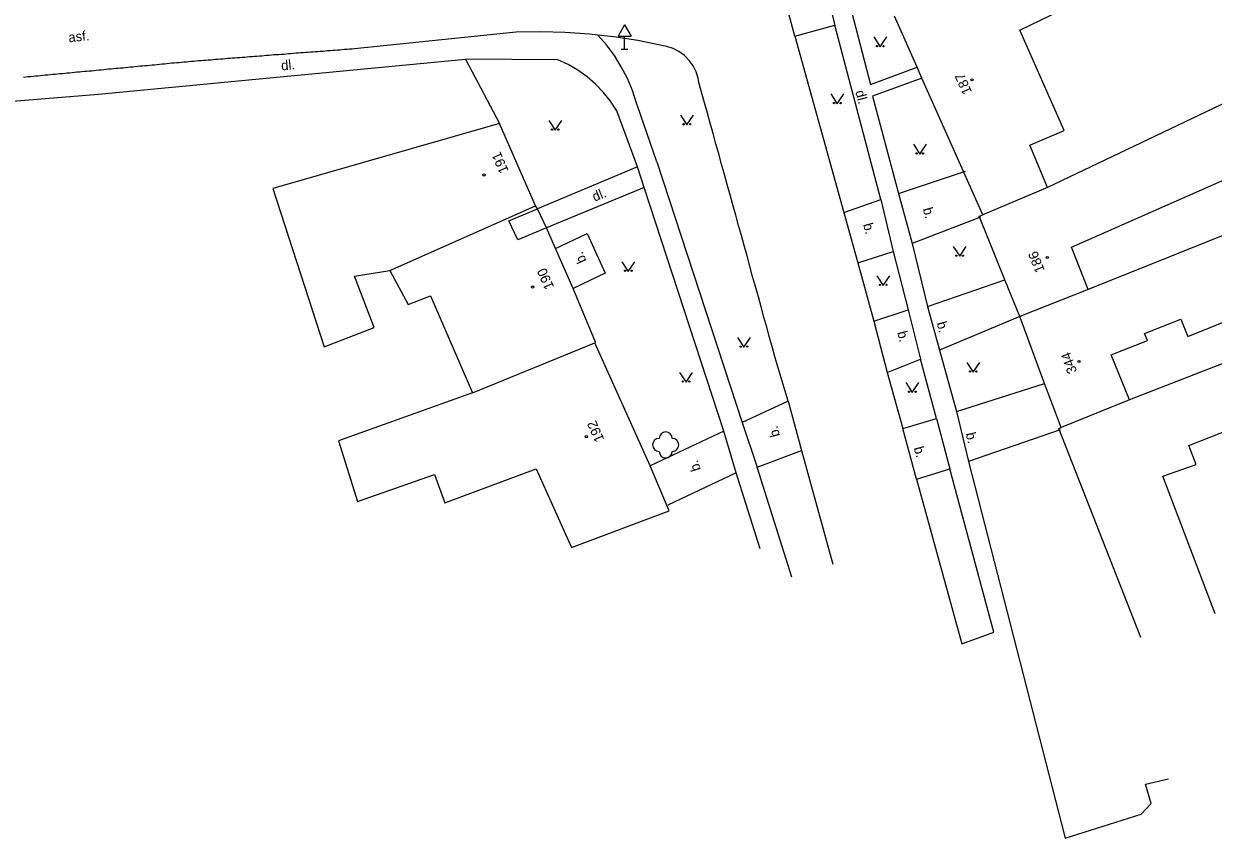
# Model space of a CAD drawing. Extents: x -536391 to -535419, y -1201788 to -1200779.
# Drawn here: x -535590.1 to -535498.7, y -1201665.1 to -1201602.5 of the extents above; entities that cross this region are included whole.
import ezdxf

# ---------------------------------------------------------------- set-up
doc = ezdxf.new("R2010")
doc.units = 0
for name, color, linetype in [('BUDOVY_MĚŘ', 7, 'Continuous'), ('BUDOVY_NEMĚŘ', 7, 'Continuous'), ('POMOC_POPIS', 7, 'Continuous'), ('ROZHRANÍ_PLOCH', 7, 'Continuous'), ('ZELEŇ', 7, 'Continuous'), ('ZN_BUDOV', 7, 'Continuous'), ('ZN_DOPLŇKOVÉ', 7, 'Continuous'), ('ZN_KULTUR', 7, 'Continuous'), ('Č_POPIS_ORIENT', 7, 'Continuous')]:
    doc.layers.add(name, color=color, linetype=linetype)

msp = doc.modelspace()

# ---------------------------------------------------------------- linework, layer by layer
at = {"layer": 'BUDOVY_MĚŘ'}
for points in [[(-535516.38, -1201617.2), (-535521.06, -1201606.7), (-535521.43, -1201605.87), (-535523.18, -1201601.94)], [(-535553.51, -1201610.19), (-535570.93, -1201615.18)], [(-535550.76, -1201616.51), (-535553.51, -1201610.19)], [(-535549.91, -1201618.2), (-535552.12, -1201619.12), (-535552.8, -1201617.68), (-535550.61, -1201616.74)], [(-535550.61, -1201616.74), (-535550.76, -1201616.51)], [(-535549.91, -1201618.2), (-535550.61, -1201616.74)], [(-535513.53, -1201625.03), (-535514.68, -1201622.21), (-535516.66, -1201617.32), (-535516.38, -1201617.2)], [(-535546.2, -1201627.04), (-535546.14, -1201627), (-535547.86, -1201622.88), (-535549.21, -1201619.8), (-535549.91, -1201618.2)], [(-535510.36, -1201633.56), (-535511.63, -1201630.16), (-535513.53, -1201625.03)], [(-535540.48, -1201639.96), (-535541.93, -1201636.51), (-535546.2, -1201627.04)], [(-535504.24, -1201649.68), (-535510.54, -1201633.63), (-535510.36, -1201633.56)]]:
    msp.add_lwpolyline(points, dxfattribs=at)
at = {"layer": 'BUDOVY_NEMĚŘ'}
for points in [[(-535511.42, -1201615.11), (-535512.76, -1201611.86), (-535510.13, -1201610.73), (-535513.53, -1201603.02), (-535501.82, -1201597.33), (-535501.47, -1201598.07), (-535500.97, -1201597.79), (-535502.17, -1201595.2), (-535503.72, -1201591.89), (-535522.9, -1201601.79)], [(-535508.29, -1201622.96), (-535509.57, -1201619.7), (-535497.15, -1201614.22), (-535497.36, -1201613.69), (-535491.66, -1201611.18), (-535493.68, -1201606.66), (-535511.42, -1201615.11), (-535516.38, -1201617.2)], [(-535505.12, -1201631.43), (-535506.53, -1201627.98), (-535503.73, -1201626.88), (-535503.95, -1201626.32), (-535501.16, -1201625.22), (-535500.63, -1201626.56), (-535492.18, -1201623.16), (-535492.7, -1201621.86), (-535491.84, -1201621.47), (-535492.19, -1201620.68), (-535480.05, -1201614.49), (-535476.82, -1201612.92), (-535479.05, -1201608.98), (-535482.17, -1201610.77), (-535494.6, -1201617.48), (-535508.29, -1201622.96), (-535513.53, -1201625.03)], [(-535570.93, -1201615.18), (-535567, -1201627.35), (-535563.15, -1201625.88), (-535564.66, -1201621.92), (-535561.95, -1201621.48), (-535550.76, -1201616.51)], [(-535561.95, -1201621.48), (-535560.53, -1201624.09), (-535558.82, -1201623.43), (-535555.6, -1201630.89), (-535546.2, -1201627.04)], [(-535498.53, -1201647.88), (-535502.55, -1201637.28), (-535499.99, -1201636.39), (-535500.56, -1201634.94), (-535486.94, -1201629.59), (-535488.98, -1201625.15), (-535505.12, -1201631.43), (-535510.36, -1201633.56)], [(-535555.6, -1201630.89), (-535565.88, -1201634.58), (-535564.42, -1201639.23), (-535558.52, -1201637.16), (-535557.71, -1201639.34), (-535550.71, -1201636.72), (-535547.98, -1201642.76), (-535540.48, -1201639.96)]]:
    msp.add_lwpolyline(points, dxfattribs=at)
at = {"layer": 'ROZHRANÍ_PLOCH'}
for points in [[(-535530.74, -1201585.15), (-535525.02, -1201607.19), (-535521.43, -1201605.87)], [(-535528.76, -1201598.67), (-535527.76, -1201602.65)], [(-535530.83, -1201603.48), (-535531.87, -1201599.53)], [(-535530.83, -1201603.48), (-535527.76, -1201602.65)], [(-535524.22, -1201616.04), (-535527.76, -1201602.65)], [(-535545.95, -1201603.4), (-535546.6, -1201603.33), (-535548.48, -1201603.2), (-535550.35, -1201603.15), (-535552.23, -1201603.18), (-535564.67, -1201604.46), (-535564.86, -1201604.48), (-535565.04, -1201604.49), (-535565.23, -1201604.5), (-535565.42, -1201604.52), (-535565.61, -1201604.53), (-535565.79, -1201604.55), (-535565.98, -1201604.56), (-535566.17, -1201604.58), (-535566.36, -1201604.59), (-535566.54, -1201604.6), (-535566.73, -1201604.62), (-535566.92, -1201604.63), (-535567.1, -1201604.65), (-535567.29, -1201604.66), (-535567.48, -1201604.68), (-535567.67, -1201604.69), (-535567.85, -1201604.7), (-535568.04, -1201604.72), (-535568.23, -1201604.73), (-535568.41, -1201604.75), (-535568.6, -1201604.76), (-535568.79, -1201604.77), (-535568.98, -1201604.79), (-535569.16, -1201604.8), (-535569.35, -1201604.82), (-535569.54, -1201604.83), (-535569.72, -1201604.85), (-535569.91, -1201604.86), (-535570.1, -1201604.88), (-535570.29, -1201604.89), (-535570.47, -1201604.91), (-535570.66, -1201604.92), (-535570.85, -1201604.93), (-535571.03, -1201604.95), (-535571.22, -1201604.96), (-535571.41, -1201604.98), (-535571.59, -1201604.99), (-535571.78, -1201605.01), (-535571.97, -1201605.02), (-535572.16, -1201605.04), (-535572.34, -1201605.05), (-535572.53, -1201605.07), (-535572.72, -1201605.08), (-535572.9, -1201605.09), (-535573.09, -1201605.11), (-535573.28, -1201605.12), (-535573.47, -1201605.14), (-535573.65, -1201605.15), (-535573.84, -1201605.17), (-535574.03, -1201605.18), (-535574.21, -1201605.2), (-535574.4, -1201605.21), (-535574.59, -1201605.23), (-535574.78, -1201605.24), (-535574.96, -1201605.25), (-535575.15, -1201605.27), (-535575.34, -1201605.28), (-535575.52, -1201605.3), (-535575.71, -1201605.32), (-535575.9, -1201605.33), (-535576.09, -1201605.34), (-535576.27, -1201605.36), (-535576.46, -1201605.37), (-535576.65, -1201605.39), (-535576.83, -1201605.4), (-535577.02, -1201605.42), (-535577.21, -1201605.43), (-535577.4, -1201605.45), (-535577.58, -1201605.47), (-535577.77, -1201605.49), (-535577.95, -1201605.5), (-535578.14, -1201605.52), (-535578.33, -1201605.54), (-535578.52, -1201605.56), (-535578.7, -1201605.57), (-535578.89, -1201605.59), (-535579.08, -1201605.61), (-535579.26, -1201605.63), (-535579.45, -1201605.64), (-535579.64, -1201605.66), (-535579.82, -1201605.68), (-535580.01, -1201605.7), (-535580.2, -1201605.72), (-535580.38, -1201605.73), (-535580.57, -1201605.75), (-535580.76, -1201605.77), (-535580.94, -1201605.79), (-535581.13, -1201605.8), (-535581.32, -1201605.82), (-535581.51, -1201605.84), (-535581.69, -1201605.86), (-535581.88, -1201605.87), (-535582.07, -1201605.89), (-535582.25, -1201605.91), (-535582.44, -1201605.93)], [(-535533.41, -1201624.29), (-535533.63, -1201623.5), (-535533.85, -1201622.72), (-535534.07, -1201621.94), (-535534.28, -1201621.15), (-535534.5, -1201620.37), (-535534.72, -1201619.58), (-535534.93, -1201618.8), (-535535.15, -1201618.02), (-535535.37, -1201617.23), (-535535.59, -1201616.45), (-535535.8, -1201615.67), (-535536.02, -1201614.88), (-535536.24, -1201614.1), (-535536.45, -1201613.31), (-535536.67, -1201612.53), (-535536.89, -1201611.75), (-535537.11, -1201610.96), (-535537.32, -1201610.18), (-535537.54, -1201609.4), (-535537.76, -1201608.61), (-535538.19, -1201607.04), (-535538.25, -1201606.71), (-535538.41, -1201606.22), (-535538.65, -1201605.76), (-535538.95, -1201605.34), (-535539.31, -1201604.98), (-535539.73, -1201604.67), (-535540.18, -1201604.43), (-535540.67, -1201604.27), (-535541.04, -1201604.19), (-535542.88, -1201603.82), (-535544.74, -1201603.53), (-535545.95, -1201603.4)], [(-535541.42, -1201613.13), (-535542.92, -1201608.83), (-535542.98, -1201608.63), (-535543.3, -1201607.67), (-535543.69, -1201606.73), (-535544.16, -1201605.83), (-535544.69, -1201604.97), (-535545.3, -1201604.16), (-535545.95, -1201603.4)], [(-535530.83, -1201603.48), (-535527.05, -1201617.02)], [(-535542.91, -1201613.52), (-535544.5, -1201609.21), (-535544.98, -1201608.48), (-535545.52, -1201607.8), (-535546.13, -1201607.17), (-535546.79, -1201606.6), (-535547.5, -1201606.1), (-535548.25, -1201605.66), (-535549.04, -1201605.29), (-535556.13, -1201605.24)], [(-535582.44, -1201605.93), (-535582.63, -1201605.95), (-535582.81, -1201605.96), (-535583, -1201605.98), (-535583.19, -1201606), (-535583.37, -1201606.01), (-535583.56, -1201606.03), (-535583.75, -1201606.05), (-535583.93, -1201606.07), (-535584.12, -1201606.09), (-535584.31, -1201606.1), (-535584.5, -1201606.12), (-535584.68, -1201606.14), (-535584.87, -1201606.16), (-535585.06, -1201606.17), (-535585.24, -1201606.19), (-535585.43, -1201606.21), (-535585.62, -1201606.23), (-535585.8, -1201606.25), (-535585.99, -1201606.26), (-535586.18, -1201606.28), (-535586.36, -1201606.3), (-535586.55, -1201606.32), (-535586.74, -1201606.33), (-535586.92, -1201606.35), (-535587.11, -1201606.37), (-535587.3, -1201606.39), (-535587.48, -1201606.4), (-535587.67, -1201606.42), (-535587.86, -1201606.44), (-535588.04, -1201606.46), (-535588.23, -1201606.48), (-535588.42, -1201606.49), (-535588.61, -1201606.51), (-535588.79, -1201606.53), (-535588.98, -1201606.55), (-535589.17, -1201606.56), (-535589.35, -1201606.58), (-535589.54, -1201606.6), (-535589.73, -1201606.62), (-535589.91, -1201606.63), (-535590.1, -1201606.65)], [(-535521.06, -1201606.7), (-535524.87, -1201608.1), (-535522.85, -1201615.58), (-535517.7, -1201613.86)], [(-535542.91, -1201613.52), (-535550.61, -1201616.74)], [(-535542.41, -1201615.11), (-535542.91, -1201613.52)], [(-535541.42, -1201613.13), (-535534.86, -1201633.17)], [(-535542.41, -1201615.11), (-535549.91, -1201618.2)], [(-535536.29, -1201633.84), (-535542.41, -1201615.11)], [(-535522.85, -1201615.58), (-535521.82, -1201619.42)], [(-535527.05, -1201617.02), (-535524.22, -1201616.04)], [(-535524.22, -1201616.04), (-535523.27, -1201620.02)], [(-535527.05, -1201617.02), (-535525.99, -1201620.9)], [(-535516.55, -1201617.4), (-535521.82, -1201619.42)], [(-535549.21, -1201619.8), (-535546.79, -1201618.64), (-535545.39, -1201621.69), (-535547.86, -1201622.88)], [(-535525.99, -1201620.9), (-535523.27, -1201620.02)], [(-535523.27, -1201620.02), (-535522.12, -1201624.5)], [(-535521.82, -1201619.42), (-535520.62, -1201624.25), (-535514.68, -1201622.21)], [(-535525.99, -1201620.9), (-535524.75, -1201625.39)], [(-535531.34, -1201631.54), (-535532.33, -1201628.21), (-535532.55, -1201627.42), (-535532.76, -1201626.64), (-535532.98, -1201625.85), (-535533.2, -1201625.07), (-535533.41, -1201624.29)], [(-535524.75, -1201625.39), (-535522.12, -1201624.5)], [(-535522.12, -1201624.5), (-535521.16, -1201628.3)], [(-535520.62, -1201624.25), (-535519.71, -1201627.6)], [(-535524.75, -1201625.39), (-535523.74, -1201629.32)], [(-535513.53, -1201625.03), (-535519.71, -1201627.6), (-535518.4, -1201632.31), (-535511.63, -1201630.16)], [(-535523.74, -1201629.32), (-535521.16, -1201628.3)], [(-535522.53, -1201633.64), (-535519.95, -1201632.86), (-535521.16, -1201628.3)], [(-535523.74, -1201629.32), (-535522.53, -1201633.64)], [(-535531.34, -1201631.54), (-535534.86, -1201633.17)], [(-535531.34, -1201631.54), (-535530.32, -1201635.31)], [(-535519.95, -1201632.86), (-535518.91, -1201636.72)], [(-535518.4, -1201632.31), (-535517.48, -1201636.17)], [(-535536.29, -1201633.84), (-535541.93, -1201636.51)], [(-535535.34, -1201637.04), (-535536.29, -1201633.84)], [(-535534.86, -1201633.17), (-535533.73, -1201636.6)], [(-535521.47, -1201637.53), (-535522.53, -1201633.64)], [(-535510.45, -1201633.72), (-535517.48, -1201636.17), (-535510.05, -1201665.11), (-535504.22, -1201663.25), (-535503.45, -1201662.44), (-535503.89, -1201660.96), (-535502.11, -1201660.54)], [(-535533.73, -1201636.6), (-535530.32, -1201635.31)], [(-535530.32, -1201635.31), (-535527.9, -1201644.06)], [(-535531.05, -1201645.04), (-535533.73, -1201636.6)], [(-535535.34, -1201637.04), (-535540.59, -1201639.52)], [(-535533.49, -1201642.88), (-535535.34, -1201637.04)], [(-535521.47, -1201637.53), (-535518.91, -1201636.72)], [(-535521.47, -1201637.53), (-535518, -1201650.17)], [(-535518, -1201650.17), (-535515.54, -1201649.28), (-535518.91, -1201636.72)]]:
    msp.add_lwpolyline(points, dxfattribs=at)
at = {"layer": 'ZELEŇ'}
msp.add_circle((-535540.75, -1201634.89), 0.0005, dxfattribs=at)
for centre, start, end in [((-535541.25, -1201634.89), 89.99999, 269.99999), ((-535540.75, -1201634.39), 0, 179.99999), ((-535540.25, -1201634.89), 270, 89.99999), ((-535540.75, -1201635.39), 179.99999, 359.99999)]:
    msp.add_arc(centre, 0.5, start, end, dxfattribs=at)
at = {"layer": 'ZN_BUDOV'}
for centre in [(-535517.21, -1201606.84), (-535554.71, -1201614.15), (-535511.43, -1201620.49), (-535550.98, -1201622.76), (-535509, -1201628.48), (-535546.85, -1201634.26)]:
    msp.add_circle(centre, 0.0875, dxfattribs=at)
at = {"layer": 'ZN_DOPLŇKOVÉ'}
for p, q in [((-535543.91, -1201602.614), (-535544.41, -1201603.48)), ((-535543.91, -1201602.614), (-535543.41, -1201603.48)), ((-535544.41, -1201603.48), (-535543.41, -1201603.48)), ((-535543.91, -1201604.48), (-535543.91, -1201603.48)), ((-535544.16, -1201604.48), (-535543.66, -1201604.48))]:
    msp.add_line(p, q, dxfattribs=at)
for points in [[(-535592.23, -1201608.58), (-535584.33, -1201607.95), (-535556.13, -1201605.24)], [(-535556.13, -1201605.24), (-535553.51, -1201610.19)]]:
    msp.add_lwpolyline(points, dxfattribs=at)
at = {"layer": 'ZN_KULTUR'}
for points in [[(-535524.76, -1201603.54), (-535524.26, -1201604.29), (-535523.76, -1201603.54)], [(-535528.06, -1201607.92), (-535527.56, -1201608.67), (-535527.06, -1201607.92)], [(-535549.74, -1201609.96), (-535549.24, -1201610.71), (-535548.74, -1201609.96)], [(-535539.62, -1201609.55), (-535539.12, -1201610.3), (-535538.62, -1201609.55)], [(-535521.72, -1201611.79), (-535521.22, -1201612.54), (-535520.72, -1201611.79)], [(-535518.66, -1201619.65), (-535518.16, -1201620.4), (-535517.66, -1201619.65)], [(-535544.12, -1201620.81), (-535543.62, -1201621.56), (-535543.12, -1201620.81)], [(-535524.53, -1201621.89), (-535524.03, -1201622.64), (-535523.53, -1201621.89)], [(-535535.24, -1201626.64), (-535534.74, -1201627.39), (-535534.24, -1201626.64)], [(-535517.62, -1201628.55), (-535517.12, -1201629.3), (-535516.62, -1201628.55)], [(-535539.68, -1201629.32), (-535539.18, -1201630.07), (-535538.68, -1201629.32)], [(-535522.3, -1201630.1), (-535521.8, -1201630.85), (-535521.3, -1201630.1)]]:
    msp.add_lwpolyline(points, dxfattribs=at)
for centre in [(-535524.51, -1201604.24), (-535524.01, -1201604.24), (-535527.81, -1201608.62), (-535527.31, -1201608.62), (-535549.49, -1201610.66), (-535548.99, -1201610.66), (-535539.37, -1201610.25), (-535538.87, -1201610.25), (-535521.47, -1201612.49), (-535520.97, -1201612.49), (-535518.41, -1201620.35), (-535517.91, -1201620.35), (-535543.87, -1201621.51), (-535543.37, -1201621.51), (-535524.28, -1201622.59), (-535523.78, -1201622.59), (-535534.99, -1201627.34), (-535534.49, -1201627.34), (-535517.37, -1201629.25), (-535516.87, -1201629.25), (-535539.43, -1201630.02), (-535538.93, -1201630.02), (-535522.05, -1201630.8), (-535521.55, -1201630.8)]:
    msp.add_circle(centre, 0.05, dxfattribs=at)

# ---------------------------------------------------------------- texts
at = {"layer": 'POMOC_POPIS'}
for s, rotation, p in [('asf.', 5.87001, (-535586.61, -1201603.96)), ('dl.', 5.49002, (-535570.26, -1201606.12)), ('dl.', 284.80999, (-535526.19, -1201607.74)), ('dl.', 22.38999, (-535546.21, -1201616.21)), ('b.', 285.01001, (-535521, -1201616.75)), ('b.', 285.27998, (-535525.59, -1201617.95)), ('b.', 114.66003, (-535546.81, -1201620.74)), ('b.', 285.2, (-535519.94, -1201625.52)), ('b.', 284.41, (-535522.96, -1201626.24)), ('b.', 105.13999, (-535531.96, -1201634.18)), ('b.', 283.41002, (-535517.7, -1201634.02)), ('b.', 285.23999, (-535521.7, -1201635.12)), ('b.', 107.70999, (-535538.05, -1201636.79))]:
    msp.add_text(s, height=0.75, rotation=rotation, dxfattribs=at).set_placement(p)
at = {"layer": 'Č_POPIS_ORIENT'}
for s, rotation, p in [('187', 113.56998, (-535517.2, -1201607.77)), ('191', 113.52001, (-535552.8, -1201613.83)), ('186', 111.51999, (-535511.61, -1201621.48)), ('190', 113.41997, (-535549.31, -1201622.76)), ('344', 109.67999, (-535509.13, -1201629.26)), ('192', 114.07, (-535545.45, -1201634.47))]:
    msp.add_text(s, height=0.75, rotation=rotation, dxfattribs=at).set_placement(p)

doc.saveas('drawing.dxf')
